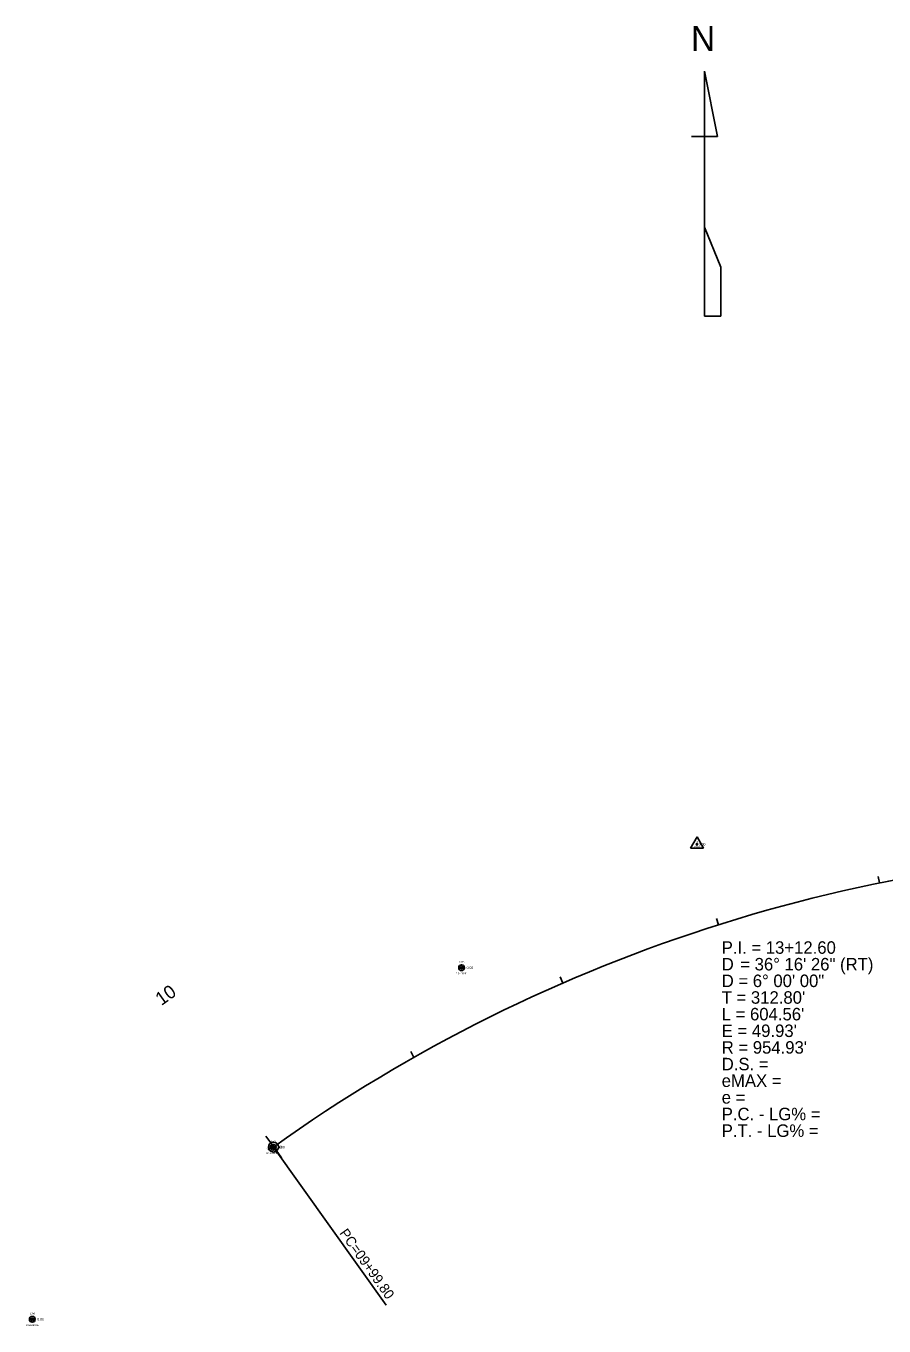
# Model space of a CAD drawing. Extents: x 2374510 to 2377726, y 1024129 to 1025429.
# Drawn here: x 2375295 to 2375811, y 1024648 to 1025429 of the extents above; entities that cross this region are included whole.
import ezdxf

# ---------------------------------------------------------------- set-up
doc = ezdxf.new("R2010")
doc.units = 0
for name, color, linetype in [('RD_EX_DV_Prop_txCode', 7, 'Continuous'), ('RD_EX_DV_PropPin', 7, 'Continuous'), ('RD_EX_Misc', 7, 'Continuous'), ('RD_EX_TX_DV_Prop_ELEV', 7, 'Continuous'), ('RD_HC_Cl', 7, 'Continuous'), ('RD_HC_Data', 7, 'Continuous'), ('RD_HC_Data_Tic', 7, 'Continuous'), ('RD_HC_Survey_ELEV', 7, 'Continuous'), ('RD_HC_TX_Sta50', 7, 'Continuous'), ('RD_HC_txCode', 7, 'Continuous'), ('RD_SMD_Locator', 7, 'Continuous')]:
    doc.layers.add(name, color=color, linetype=linetype)

msp = doc.modelspace()

# ---------------------------------------------------------------- linework, layer by layer
at = {"layer": 'RD_EX_DV_PropPin'}
for p, q in [((2375555.95, 1024863.43), (2375555.95, 1024863.82)), ((2375555.99, 1024863.32), (2375555.99, 1024863.92)), ((2375556.02, 1024863.25), (2375556.02, 1024863.99)), ((2375556.06, 1024863.19), (2375556.06, 1024864.05)), ((2375556.09, 1024863.15), (2375556.09, 1024864.1)), ((2375556.13, 1024863.11), (2375556.13, 1024864.14)), ((2375556.16, 1024863.07), (2375556.16, 1024864.17)), ((2375556.2, 1024863.04), (2375556.2, 1024864.2)), ((2375556.23, 1024863.01), (2375556.23, 1024864.23)), ((2375556.27, 1024862.99), (2375556.27, 1024864.26)), ((2375556.3, 1024862.97), (2375556.3, 1024864.28)), ((2375556.34, 1024862.95), (2375556.34, 1024864.3)), ((2375556.37, 1024862.93), (2375556.37, 1024864.31)), ((2375556.41, 1024862.91), (2375556.41, 1024864.33)), ((2375556.44, 1024862.9), (2375556.44, 1024864.34)), ((2375556.48, 1024862.89), (2375556.48, 1024864.35)), ((2375556.51, 1024862.88), (2375556.51, 1024864.36)), ((2375556.55, 1024862.87), (2375556.55, 1024864.37)), ((2375556.58, 1024862.87), (2375556.58, 1024864.38)), ((2375556.62, 1024862.86), (2375556.62, 1024864.38)), ((2375556.65, 1024862.86), (2375556.65, 1024864.38)), ((2375556.69, 1024862.86), (2375556.69, 1024864.38)), ((2375556.72, 1024862.86), (2375556.72, 1024864.38)), ((2375556.76, 1024862.86), (2375556.76, 1024864.38)), ((2375556.79, 1024862.87), (2375556.79, 1024864.38)), ((2375556.83, 1024862.87), (2375556.83, 1024864.37)), ((2375556.86, 1024862.88), (2375556.86, 1024864.36)), ((2375556.9, 1024862.89), (2375556.9, 1024864.35)), ((2375556.93, 1024862.9), (2375556.93, 1024864.34)), ((2375556.97, 1024862.91), (2375556.97, 1024864.33)), ((2375557, 1024862.93), (2375557, 1024864.31)), ((2375557.04, 1024862.95), (2375557.04, 1024864.3)), ((2375557.07, 1024862.97), (2375557.07, 1024864.28)), ((2375557.11, 1024862.99), (2375557.11, 1024864.26)), ((2375557.14, 1024863.01), (2375557.14, 1024864.23)), ((2375557.18, 1024863.04), (2375557.18, 1024864.2)), ((2375557.21, 1024863.07), (2375557.21, 1024864.17)), ((2375557.25, 1024863.11), (2375557.25, 1024864.14)), ((2375557.28, 1024863.15), (2375557.28, 1024864.1)), ((2375557.32, 1024863.19), (2375557.32, 1024864.05)), ((2375557.35, 1024863.25), (2375557.35, 1024863.99)), ((2375557.39, 1024863.32), (2375557.39, 1024863.92)), ((2375557.42, 1024863.43), (2375557.42, 1024863.82)), ((2375442.71, 1024755.58), (2375442.71, 1024755.97)), ((2375442.75, 1024755.48), (2375442.75, 1024756.08)), ((2375442.78, 1024755.41), (2375442.78, 1024756.15)), ((2375442.82, 1024755.35), (2375442.82, 1024756.2)), ((2375442.85, 1024755.3), (2375442.85, 1024756.25)), ((2375442.89, 1024755.26), (2375442.89, 1024756.29)), ((2375442.92, 1024755.23), (2375442.92, 1024756.33)), ((2375442.96, 1024755.2), (2375442.96, 1024756.36)), ((2375442.99, 1024755.17), (2375442.99, 1024756.39)), ((2375443.03, 1024755.14), (2375443.03, 1024756.41)), ((2375443.06, 1024755.12), (2375443.06, 1024756.43)), ((2375443.1, 1024755.1), (2375443.1, 1024756.45)), ((2375443.13, 1024755.09), (2375443.13, 1024756.47)), ((2375443.17, 1024755.07), (2375443.17, 1024756.49)), ((2375443.2, 1024755.06), (2375443.2, 1024756.5)), ((2375443.24, 1024755.05), (2375443.24, 1024756.51)), ((2375443.27, 1024755.04), (2375443.27, 1024756.52)), ((2375443.31, 1024755.03), (2375443.31, 1024756.53)), ((2375443.34, 1024755.02), (2375443.34, 1024756.53)), ((2375443.38, 1024755.02), (2375443.38, 1024756.54)), ((2375443.41, 1024755.02), (2375443.41, 1024756.54)), ((2375443.45, 1024755.02), (2375443.45, 1024756.54)), ((2375443.48, 1024755.02), (2375443.48, 1024756.54)), ((2375443.52, 1024755.02), (2375443.52, 1024756.54)), ((2375443.55, 1024755.02), (2375443.55, 1024756.53)), ((2375443.59, 1024755.03), (2375443.59, 1024756.53)), ((2375443.62, 1024755.04), (2375443.62, 1024756.52)), ((2375443.66, 1024755.05), (2375443.66, 1024756.51)), ((2375443.69, 1024755.06), (2375443.69, 1024756.5)), ((2375443.73, 1024755.07), (2375443.73, 1024756.49)), ((2375443.76, 1024755.09), (2375443.76, 1024756.47)), ((2375443.8, 1024755.1), (2375443.8, 1024756.45)), ((2375443.83, 1024755.12), (2375443.83, 1024756.43)), ((2375443.87, 1024755.14), (2375443.87, 1024756.41)), ((2375443.9, 1024755.17), (2375443.9, 1024756.39)), ((2375443.94, 1024755.2), (2375443.94, 1024756.36)), ((2375443.97, 1024755.23), (2375443.97, 1024756.33)), ((2375444.01, 1024755.26), (2375444.01, 1024756.29)), ((2375444.04, 1024755.3), (2375444.04, 1024756.25)), ((2375444.08, 1024755.35), (2375444.08, 1024756.2)), ((2375444.11, 1024755.41), (2375444.11, 1024756.15)), ((2375444.15, 1024755.48), (2375444.15, 1024756.08)), ((2375444.18, 1024755.58), (2375444.18, 1024755.97)), ((2375298.01, 1024652.23), (2375298.01, 1024652.62)), ((2375298.04, 1024652.13), (2375298.04, 1024652.72)), ((2375298.08, 1024652.06), (2375298.08, 1024652.8)), ((2375298.11, 1024652), (2375298.11, 1024652.85)), ((2375298.15, 1024651.95), (2375298.15, 1024652.9)), ((2375298.18, 1024651.91), (2375298.18, 1024652.94)), ((2375298.22, 1024651.88), (2375298.22, 1024652.98)), ((2375298.25, 1024651.84), (2375298.25, 1024653.01)), ((2375298.29, 1024651.82), (2375298.29, 1024653.04)), ((2375298.32, 1024651.79), (2375298.32, 1024653.06)), ((2375298.36, 1024651.77), (2375298.36, 1024653.08)), ((2375298.39, 1024651.75), (2375298.39, 1024653.1)), ((2375298.43, 1024651.73), (2375298.43, 1024653.12)), ((2375298.46, 1024651.72), (2375298.46, 1024653.13)), ((2375298.5, 1024651.71), (2375298.5, 1024653.15)), ((2375298.53, 1024651.69), (2375298.53, 1024653.16)), ((2375298.57, 1024651.69), (2375298.57, 1024653.17)), ((2375298.6, 1024651.68), (2375298.6, 1024653.17)), ((2375298.64, 1024651.67), (2375298.64, 1024653.18)), ((2375298.67, 1024651.67), (2375298.67, 1024653.18)), ((2375298.71, 1024651.67), (2375298.71, 1024653.19)), ((2375298.74, 1024651.66), (2375298.74, 1024653.19)), ((2375298.78, 1024651.67), (2375298.78, 1024653.19)), ((2375298.81, 1024651.67), (2375298.81, 1024653.18)), ((2375298.85, 1024651.67), (2375298.85, 1024653.18)), ((2375298.88, 1024651.68), (2375298.88, 1024653.17)), ((2375298.92, 1024651.69), (2375298.92, 1024653.17)), ((2375298.95, 1024651.69), (2375298.95, 1024653.16)), ((2375298.99, 1024651.71), (2375298.99, 1024653.15)), ((2375299.02, 1024651.72), (2375299.02, 1024653.13)), ((2375299.06, 1024651.73), (2375299.06, 1024653.12)), ((2375299.09, 1024651.75), (2375299.09, 1024653.1)), ((2375299.13, 1024651.77), (2375299.13, 1024653.08)), ((2375299.16, 1024651.79), (2375299.16, 1024653.06)), ((2375299.2, 1024651.82), (2375299.2, 1024653.04)), ((2375299.23, 1024651.84), (2375299.23, 1024653.01)), ((2375299.27, 1024651.88), (2375299.27, 1024652.98)), ((2375299.3, 1024651.91), (2375299.3, 1024652.94)), ((2375299.34, 1024651.95), (2375299.34, 1024652.9)), ((2375299.37, 1024652), (2375299.37, 1024652.85)), ((2375299.41, 1024652.06), (2375299.41, 1024652.8)), ((2375299.44, 1024652.13), (2375299.44, 1024652.72)), ((2375299.48, 1024652.23), (2375299.48, 1024652.62))]:
    msp.add_line(p, q, dxfattribs=at)
for centre, radius in [((2375556.69, 1024863.62), 1.75), ((2375556.69, 1024863.62), 0.761), ((2375443.45, 1024755.78), 1.75), ((2375443.45, 1024755.78), 0.761), ((2375298.74, 1024652.43), 1.75), ((2375298.74, 1024652.43), 0.761)]:
    msp.add_circle(centre, radius, dxfattribs=at)
at = {"layer": 'RD_EX_Misc'}
for p, q in [((2375710.55, 1025362.88), (2375702.71, 1025402.08)), ((2375702.71, 1025402.08), (2375702.71, 1025402.08)), ((2375702.71, 1025402.08), (2375702.71, 1025362.88)), ((2375694.87, 1025362.88), (2375702.71, 1025362.88)), ((2375702.71, 1025308.48), (2375702.71, 1025362.88)), ((2375702.71, 1025362.88), (2375710.55, 1025362.88)), ((2375710.55, 1025362.88), (2375710.55, 1025363.34)), ((2375712.51, 1025284.48), (2375702.71, 1025308.48)), ((2375702.71, 1025308.48), (2375702.71, 1025255.07)), ((2375712.51, 1025255.07), (2375712.51, 1025284.75)), ((2375712.51, 1025284.75), (2375712.51, 1025284.48)), ((2375702.71, 1025255.07), (2375712.51, 1025255.07))]:
    msp.add_line(p, q, dxfattribs=at)
at = {"layer": 'RD_HC_Cl'}
msp.add_arc((2375998.65, 1023978.84), 954.93, 89.26234, 125.53622, dxfattribs=at)
at = {"layer": 'RD_HC_Data'}
for p, q in [((2375694.2, 1024935.42), (2375698.17, 1024942.3)), ((2375698.17, 1024942.3), (2375702.14, 1024935.42)), ((2375694.2, 1024935.42), (2375702.14, 1024935.42)), ((2375443.63, 1024755.91), (2375511.45, 1024660.95))]:
    msp.add_line(p, q, dxfattribs=at)
for centre, radius in [((2375698.17, 1024937.72), 0.529), ((2375443.63, 1024755.91), 3), ((2375443.63, 1024755.91), 0.282)]:
    msp.add_circle(centre, radius, dxfattribs=at)
at = {"layer": 'RD_HC_Data_Tic'}
for p, q in [((2375807.87, 1024914.52), (2375807.08, 1024918.44)), ((2375711.11, 1024889.45), (2375709.91, 1024893.26)), ((2375617.51, 1024854.41), (2375615.91, 1024858.07)), ((2375528.07, 1024809.77), (2375526.1, 1024813.25)), ((2375443.79, 1024756.03), (2375439.15, 1024762.54)), ((2375443.79, 1024756.03), (2375448.44, 1024749.52))]:
    msp.add_line(p, q, dxfattribs=at)
at = {"layer": 'RD_SMD_Locator'}
for centre in [(2375698.17, 1024937.72), (2375556.69, 1024863.62), (2375443.45, 1024755.78), (2375443.63, 1024755.91), (2375298.74, 1024652.43)]:
    msp.add_circle(centre, 0.15, dxfattribs=at)

# ---------------------------------------------------------------- texts
at = {"layer": 'RD_EX_DV_Prop_txCode'}
for s, p in [('1003', (2375555.26, 1024866.62)), ('IP 3/4PIPE', (2375552.78, 1024859.62)), ('IP RRSPIKE', (2375439.53, 1024751.78)), ('1002', (2375442.02, 1024758.78)), ('1000', (2375297.28, 1024655.43)), ('IP RRSPIKE', (2375294.83, 1024648.43))]:
    msp.add_text(s, height=1, dxfattribs=at).set_placement(p)
at = {"layer": 'RD_EX_Misc'}
msp.add_text('N', height=15, dxfattribs=at).set_placement((2375694.56, 1025414.29))
at = {"layer": 'RD_EX_TX_DV_Prop_ELEV'}
for p in [(2375559.69, 1024862.87), (2375446.45, 1024755.03), (2375301.74, 1024651.68)]:
    msp.add_text('0.00', height=1.5, dxfattribs=at).set_placement(p)
at = {"layer": 'RD_HC_Data'}
for s, p in [('P.I. = 13+12.60', (2375713, 1024872)), ('    = 36%%d 16\' 26" (RT)', (2375713, 1024862)), ('D', (2375713, 1024862)), ('D = 6%%d 00\' 00"', (2375713, 1024852)), ("T = 312.80'", (2375713, 1024842)), ("L = 604.56'", (2375713, 1024832)), ("E = 49.93'", (2375713, 1024822)), ("R = 954.93'", (2375713, 1024812)), ('D.S. = ', (2375713, 1024802)), ('eMAX = ', (2375713, 1024792)), ('e = ', (2375713, 1024782)), ('P.C. - LG% = ', (2375713, 1024772)), ('P.T. - LG% = ', (2375713, 1024762))]:
    msp.add_text(s, height=7.5, dxfattribs=at).set_placement(p)
msp.add_text('PC=09+99.80', height=6, rotation=305.53622, dxfattribs=at).set_placement((2375483.04, 1024704.18))
at = {"layer": 'RD_HC_Survey_ELEV'}
for p in [(2375699.17, 1024936.97), (2375444.63, 1024755.16)]:
    msp.add_text('0.00', height=1.5, dxfattribs=at).set_placement(p)
at = {"layer": 'RD_HC_TX_Sta50'}
msp.add_text('10', height=8, rotation=35.52422, dxfattribs=at).set_placement((2375376.32, 1024840.56))
at = {"layer": 'RD_HC_txCode'}
for s, p in [('PI 13+12.60', (2375694.61, 1024935.72)), ('4', (2375697.89, 1024938.72)), ('PC 9+99.80', (2375439.36, 1024753.91)), ('3', (2375443.35, 1024756.91))]:
    msp.add_text(s, height=1, dxfattribs=at).set_placement(p)

doc.saveas('drawing.dxf')
